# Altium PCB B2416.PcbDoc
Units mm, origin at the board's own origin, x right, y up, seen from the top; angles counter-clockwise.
Board outline 43 x 50 mm, 4 copper layers (Top Layer, Internal 1, Internal 2, Bottom Layer), stack 1.565 mm thick; 60 components, 49 nets, 260 pads, 194 vias.
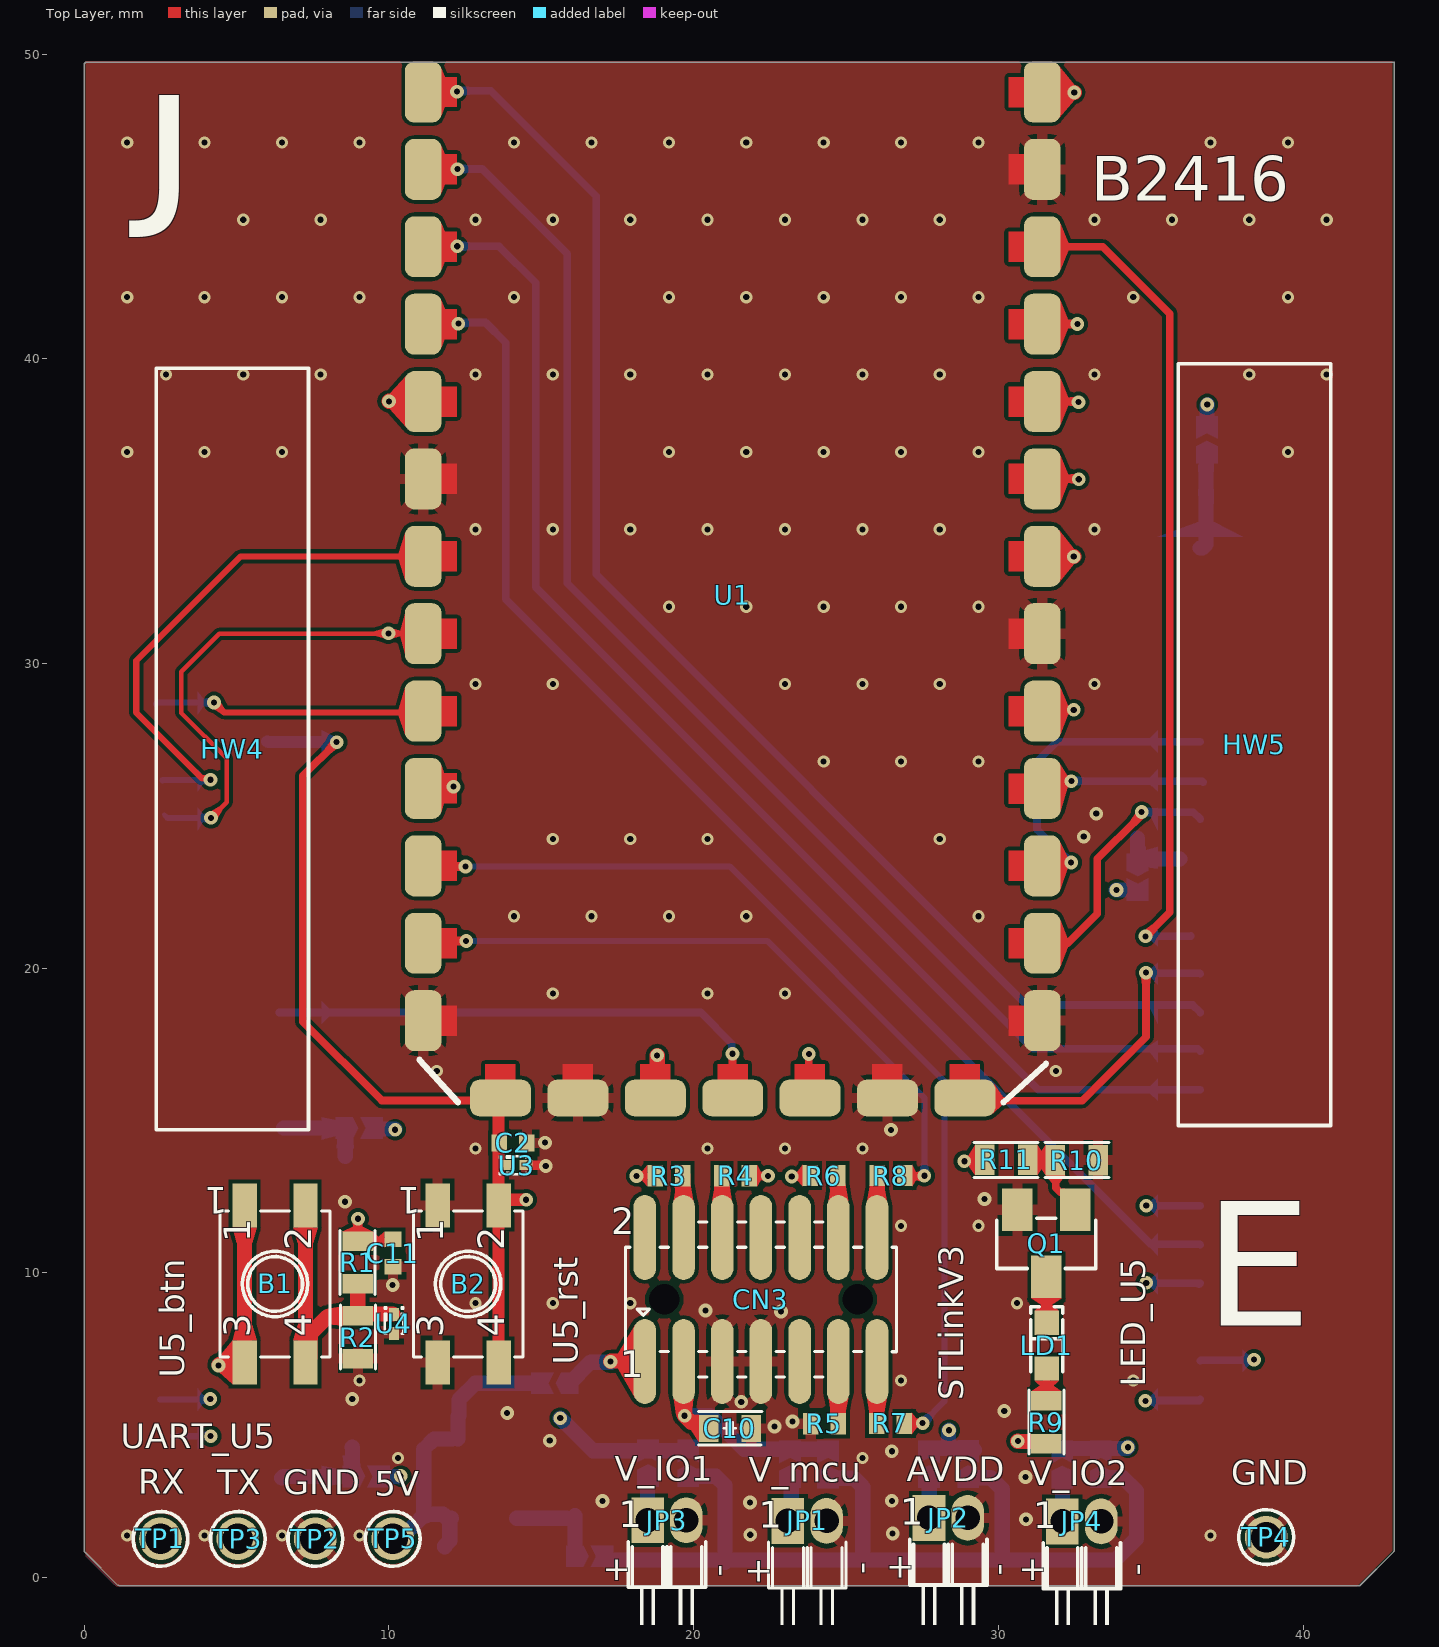
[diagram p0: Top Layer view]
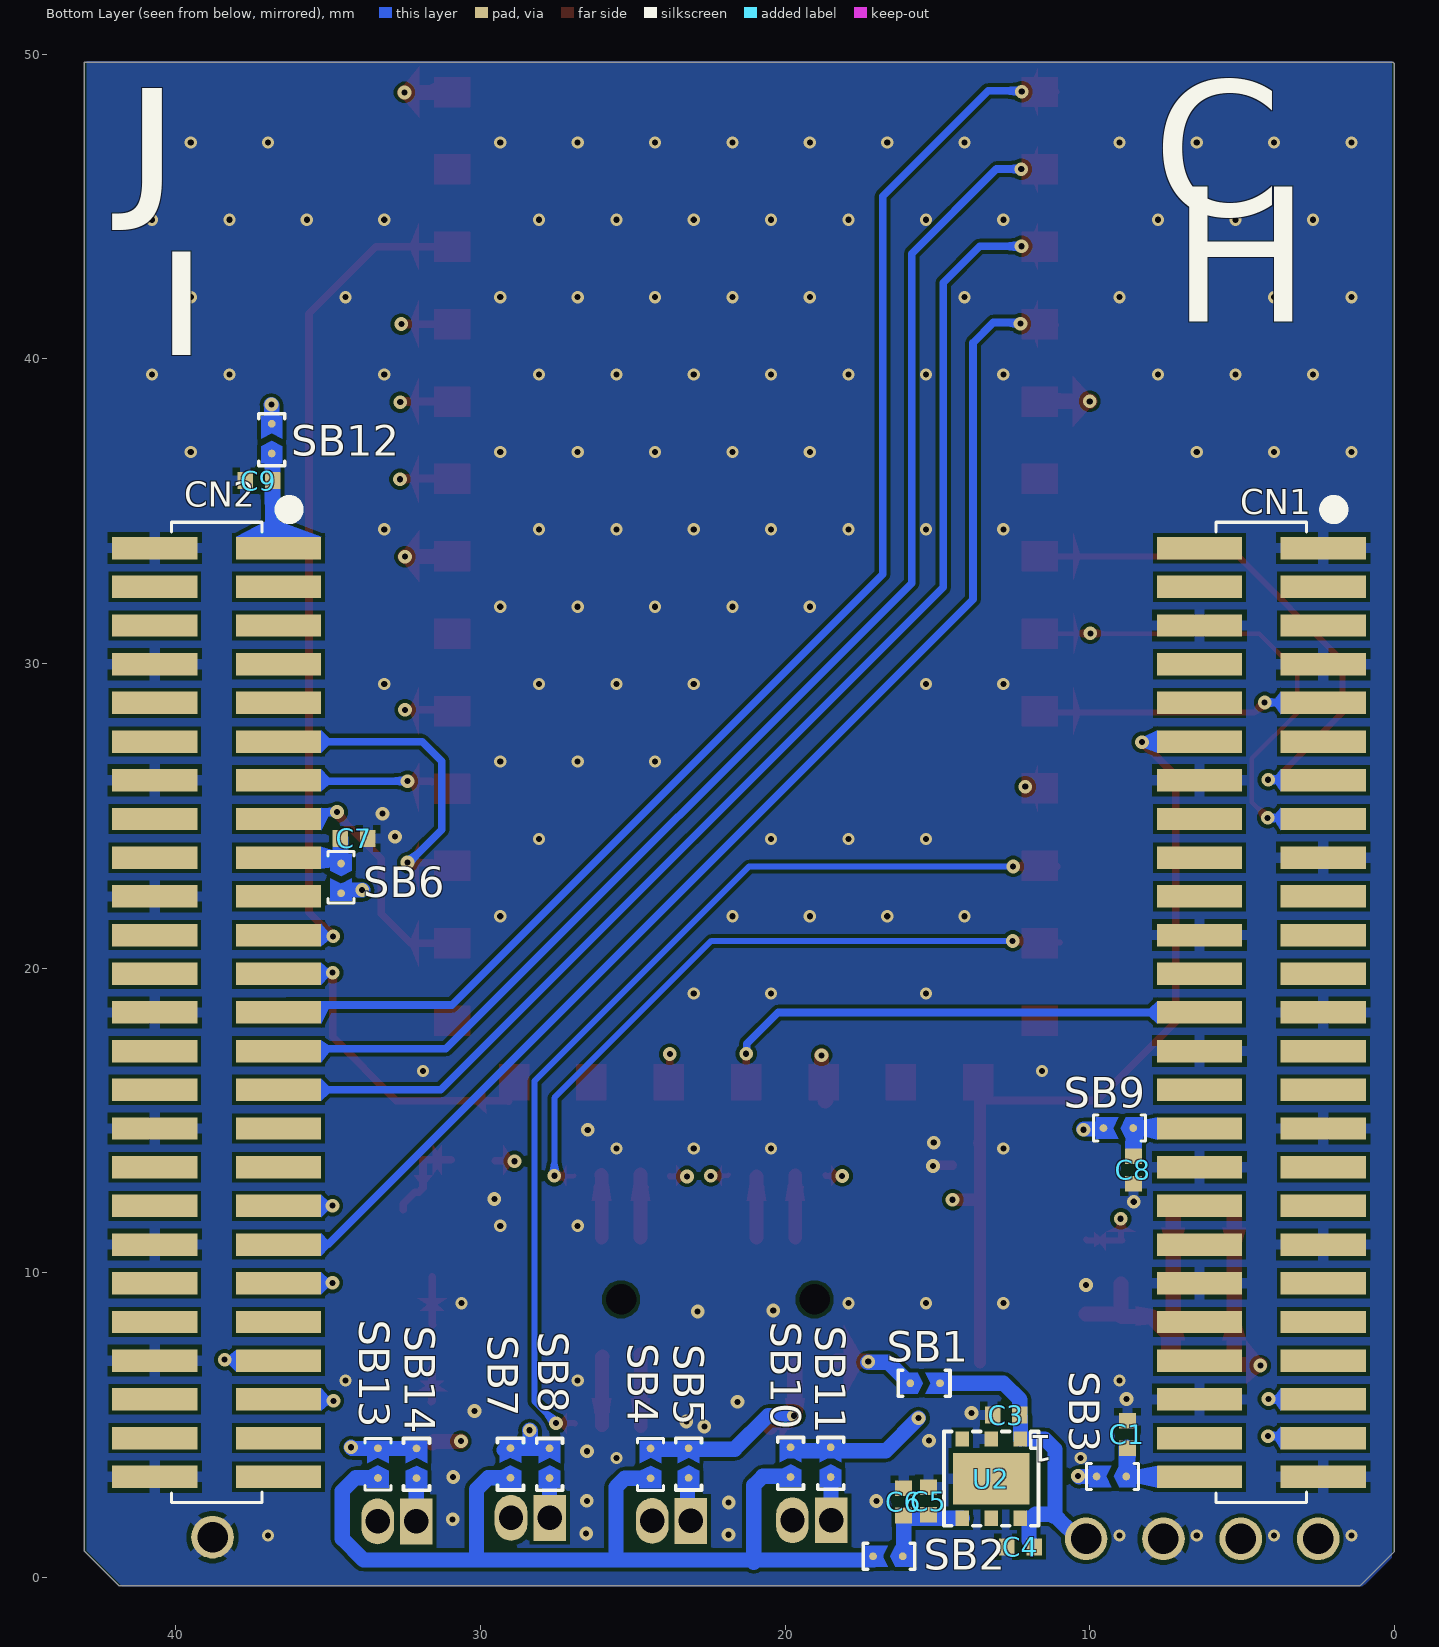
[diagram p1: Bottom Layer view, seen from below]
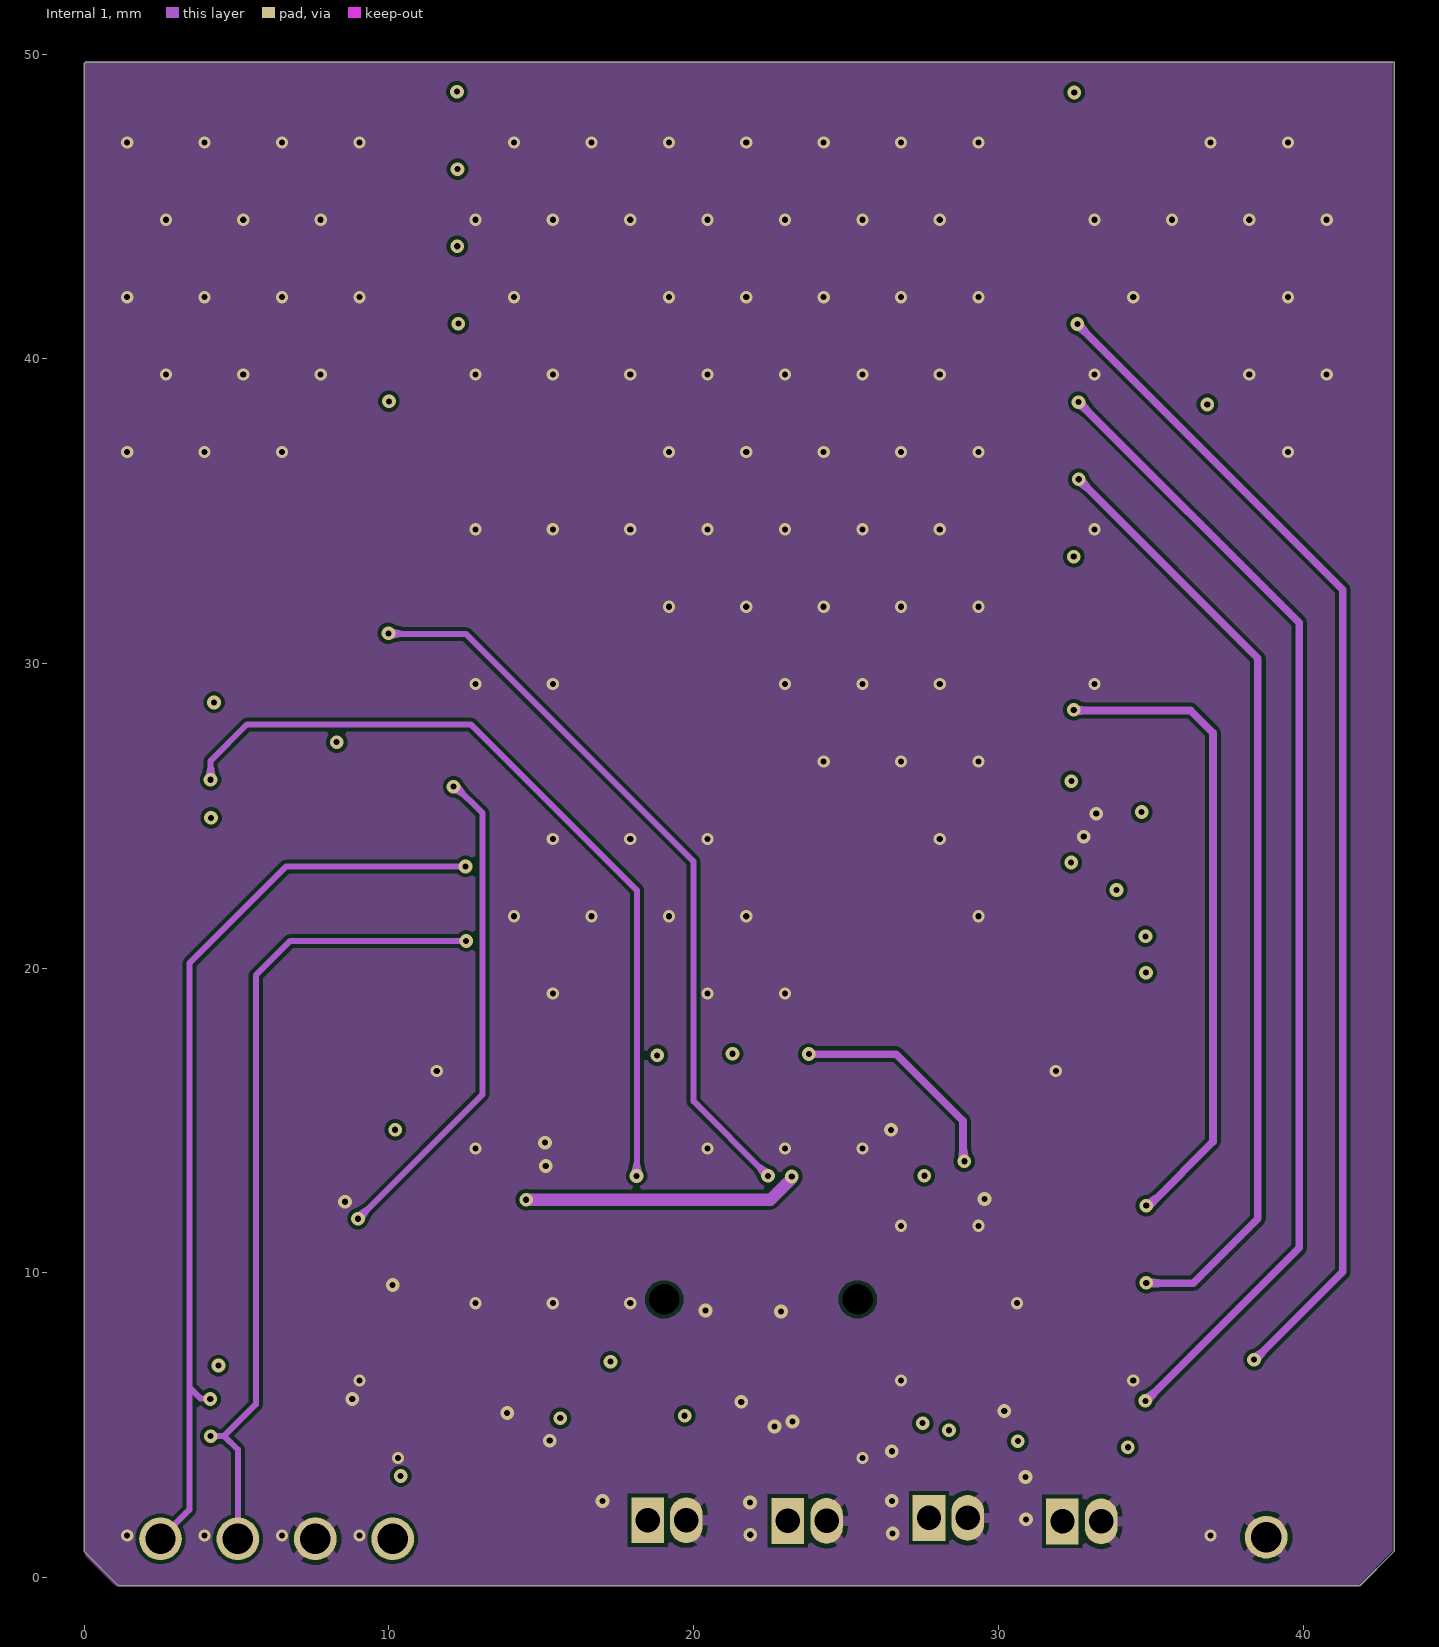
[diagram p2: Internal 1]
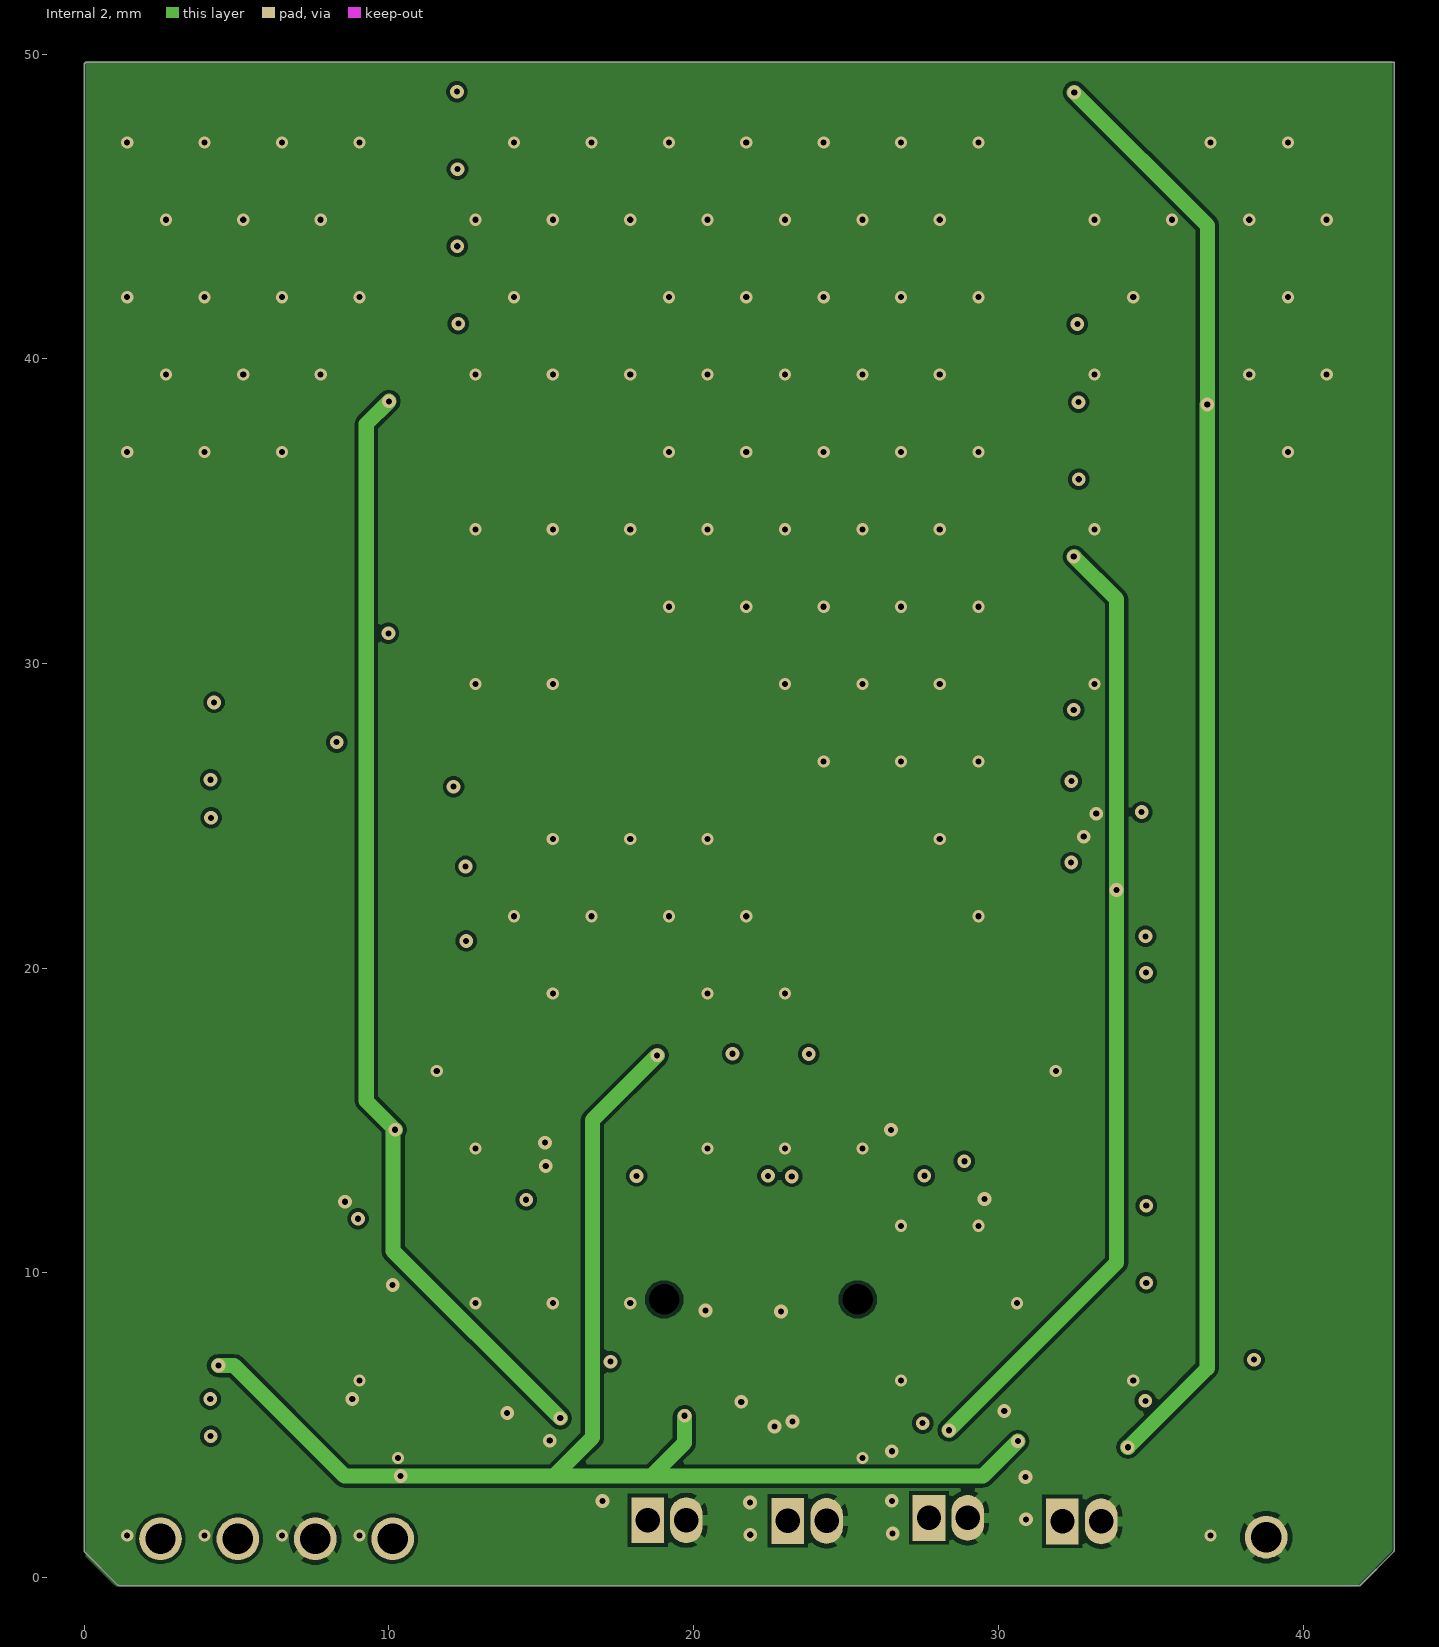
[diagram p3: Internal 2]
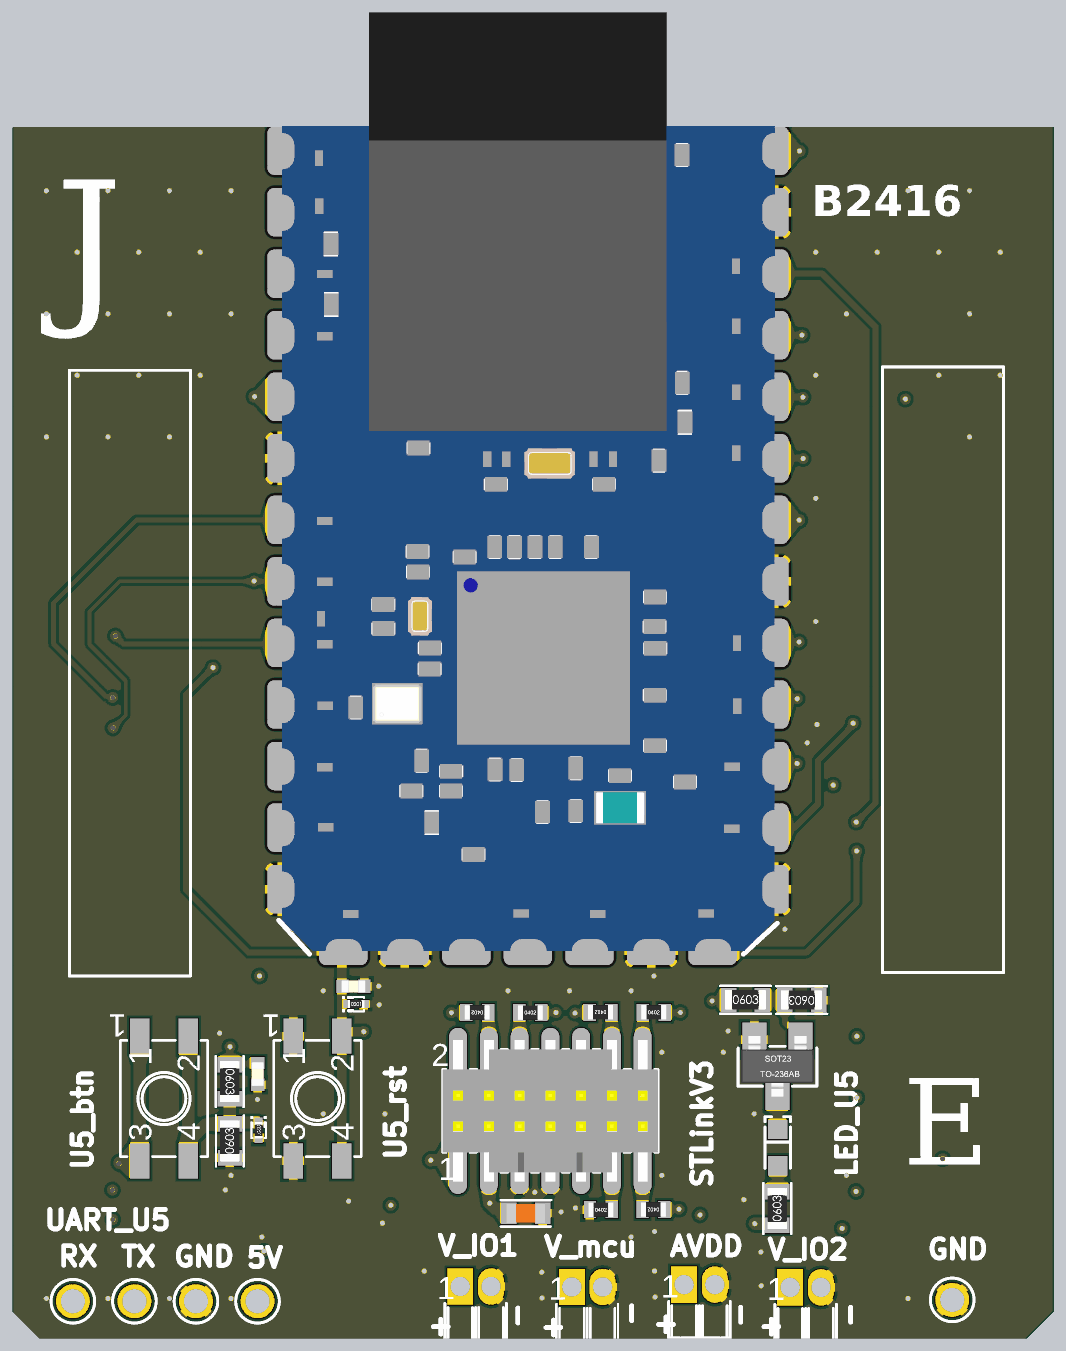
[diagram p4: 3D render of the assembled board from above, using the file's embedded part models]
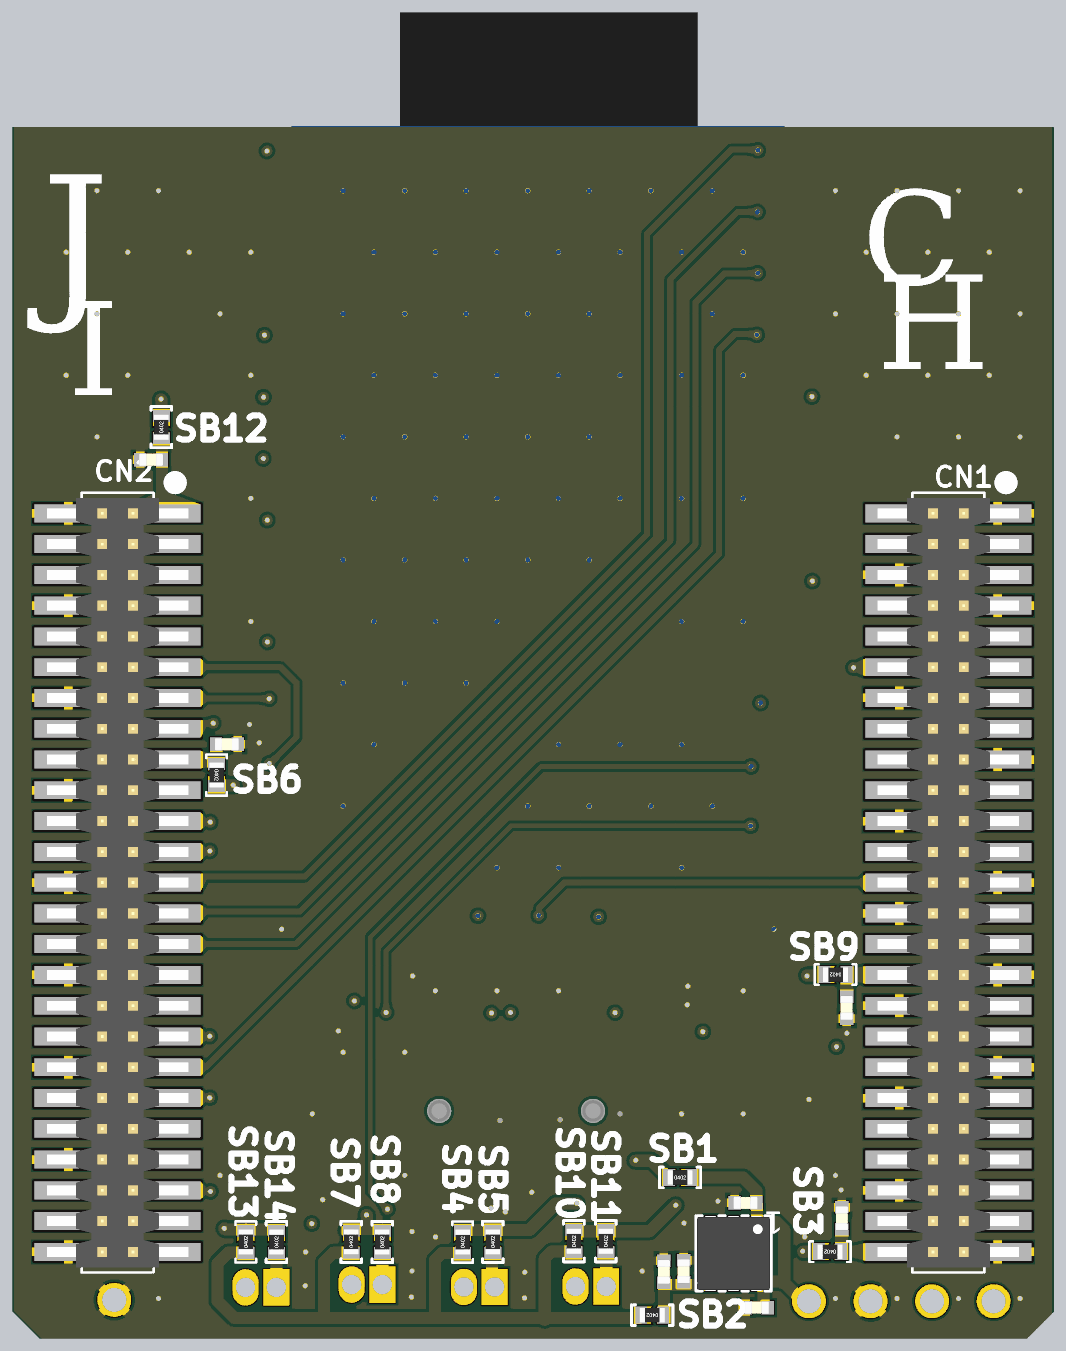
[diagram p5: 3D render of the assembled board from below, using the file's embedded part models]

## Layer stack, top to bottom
Top Solder: solder mask 0.0178, Solder Resist, Dk 3.2
Top Layer: signal copper 0.0406
Dielectric 1: core 0.0762, FR-4, Dk 3.7
Internal 1: signal copper 0.0305
Dielectric 3: prepreg 1.27, Dk 4.5
Internal 2: signal copper 0.0305
Dielectric 2: core 0.0762, Dk 3.7
Bottom Layer: signal copper 0.0406
Bottom Solder: solder mask 0.0178, Solder Resist, Dk 4.2

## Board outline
0,0.852 1.11,-0.258 1.126,-0.258 1.134,-0.267 41.86,-0.267 42.986,0.86 42.995,0.868 43,0.868 43,49.728 42.994,49.733 0.044,49.733 0,49.689

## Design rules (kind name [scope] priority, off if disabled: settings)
Clearance "RF Path 4" [InNet('NetC48_2')] p1: gap=0.125 ignorepadtopadclearanceinfootprint=FALSE
Clearance "RF Path 3" [InNet('NetR12_1')] p2: gap=0.125 ignorepadtopadclearanceinfootprint=FALSE
Clearance "RF Path 2" [InNet('RF_out_ufl')] p3: gap=0.125 ignorepadtopadclearanceinfootprint=FALSE
Clearance "RF Path 1" [InNet('NetR11_1')] p4: gap=0.125 ignorepadtopadclearanceinfootprint=FALSE
Clearance [All] p5: gap=0.12 ignorepadtopadclearanceinfootprint=FALSE
ComponentClearance [All] p1: gap=0.2 collisioncheckmode=3 verticalgap=0.2 showdistances=FALSE
HoleSize [All] p1: absolutevalues=TRUE maxlimit=10 minlimit=0.025 maxpercent=80.000 minpercent=20.000
MinimumSolderMaskSliver [All] p1: minsoldermaskwidth=0.1
PlaneConnect [All] p1: planeconnectstyle=Relief reliefexpansion=0.508 reliefentries=4 reliefconductorwidth=0.21 reliefairgap=0.21
PolygonConnect Path_RF [InNet('NetC12_2')] p1: connectstyle=Direct reliefconductorwidth=0.254 reliefentries=4 polygonreliefangle="90 Angle" airgapwidth=0.254
PolygonConnect PolygonConnect_via [IsVia] p2: connectstyle=Direct reliefconductorwidth=0.254 reliefentries=4 polygonreliefangle="90 Angle" airgapwidth=0.254
PolygonConnect General [All] p3: connectstyle=Relief reliefconductorwidth=0.35 reliefentries=4 polygonreliefangle="90 Angle" conductorbypadedge=TRUE mindistance=0.381 enablemindistance=FALSE airgapwidth=0.15
RoutingVias [All] p1: holewidth=0.3 width=0.8 viastyle="Through Hole" minholewidth=0.1 minwidth=0.2 maxholewidth=3.5 maxwidth=6.5
SilkToSilkClearance [All] p1 off: silktosilkclearance=0.2
SilkToSolderMaskClearance [IsPad] p1 off: minsilkscreentomaskgap=0.2 clearancetoexposedcopper=TRUE
SolderMaskExpansion [All] p1: expansion=0.102 istentingtop=FALSE
Width [All] p1: maxlimit=6 minlimit=0.1 preferedwidth=0.3 minimp=50.000000 maximp=50.000000 favimp=50.000000
24 further rules are at their usual default settings.

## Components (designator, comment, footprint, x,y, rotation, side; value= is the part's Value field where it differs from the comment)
B1 "SW-PUSH-CMS_EVQP2_BLACK" SWI_PANASONIC_EVQP2F02K 6.26,9.636 r90 top value=EVQP2F02K
B2 "SW-PUSH-CMS_EVQP2_BLACK" SWI_PANASONIC_EVQP2F02K 12.597,9.636 r90 top value=EVQP2F02K
C1 "Capacitor" C0402 8.763,4.699 r270 bottom value=10uF
C2 "" C0402 14.076,14.265 r180 top value=100nF
C3 "Capacitor" C0402 12.74,5.333 r180 bottom value=1uF
C4 "Capacitor" C0402 12.271,1.007 r180 bottom value=100nF
C5 "Capacitor" C0402 15.291,2.511 r270 bottom value=1uF
C6 "Capacitor" C0402 16.106,2.487 r270 bottom value=100nF
C7 "Capacitor" C0402 34.143,24.26 r0 bottom value=10uF
C8 "Capacitor" C0402 8.564,13.381 r270 bottom value=10uF
C9 "Capacitor" C0402 37.27,36.001 r0 bottom value=10uF
C10 "Capacitor" C0603 21.189,4.897 r180 top value=1uF
C11 "" C0402 10.128,10.651 r90 top value=100nF
CART-1 "Comment" Sheetbox_6L2S -0.159,-32.344 r0 top
CN1 "FTSH-125-02-L-DV" FTSH-125-02-L-DV 4.366,18.548 r180 bottom locked value="Header 25x2"
CN2 "FTSH-125-02-L-DV" FTSH-125-02-L-DV 38.656,18.548 r180 bottom locked value="Header 25x2"
CN3 "Header 7x2" CON_SAMTEC_FTSH-107-01-L-DV-K-A 22.207,9.127 r0 top
Designator1 "Comment" PCB_SPECIFICATIONS 48.372,6.833 r0 top
HW4 "STICKER_PRODUCT" STICKER_PRODUCT_25X5 4.857,27.194 r90 top value="Sticker product"
HW5 "STICKER_BOARD" STICKER_BOARD_25X5 38.408,27.336 r90 top value="Sticker product"
JP1 "Jumper_Header1.27 2x1 Fitted" CON_WP_707-2-02-2-20-00 23.728,1.859 r0 top value="Header 2x1"
JP2 "Jumper_Header1.27 2x1 Fitted" CON_WP_707-2-02-2-20-00 28.36,1.958 r0 top value="Header 2x1"
JP3 "Jumper_Header1.27 2x1 Fitted" CON_WP_707-2-02-2-20-00 19.123,1.879 r0 top value="Header 2x1"
JP4 "Jumper_Header1.27 2x1 Fitted" CON_WP_707-2-02-2-20-00 32.739,1.842 r0 top value="Header 2x1"
LD1 "LED_red" LED_0603_OSRAM_LS-Q976-NR-1_RED_1A2K_H0P8 31.59,7.61 r90 top value=Red
Q1 "" NPN_SOT23 31.578,10.971 r180 top value=9013-SOT23
R1 "" R0603 8.97,10.337 r270 top value=330R
R2 "" R0603 8.981,7.888 r90 top value=100K
R3 "Resistor" R0402 19.186,13.188 r180 top value=47R
R4 "Resistor" R0402 21.379,13.186 r0 top value=47R
R5 "Resistor" R0402 24.291,5.049 r0 top value=47R
R6 "Resistor" R0402 24.275,13.195 r180 top value=47R
R7 "Resistor" R0402 26.458,5.057 r180 top value=47R
R8 "Resistor" R0402 26.475,13.194 r0 top value=47R
R9 "" R0603 31.574,5.099 r90 top value=1K
R10 "" R0603 32.576,13.703 r180 top value=100K
R11 "" R0603 30.259,13.708 r0 top value=47K
SB1 "SB_ON" SOLDER-BRIDGE_R0402-0R 15.438,6.378 r180 bottom value=0R
SB2 "SB_ON" SOLDER-BRIDGE_R0402-0R 16.588,0.697 r0 bottom value=0R
SB3 "SB_OFF" SOLDER-BRIDGE_R0402-0R 9.251,3.317 r0 bottom
SB4 "SB_ON" SOLDER-BRIDGE_R0402-0R 24.414,3.712 r90 bottom value=0R
SB5 "SB_OFF" SOLDER-BRIDGE_R0402-0R 23.166,3.721 r90 bottom
SB6 "SB_OFF" SOLDER-BRIDGE_R0402-0R 34.572,22.986 r270 bottom
SB7 "SB_ON" SOLDER-BRIDGE_R0402-0R 29.012,3.723 r90 bottom value=0R
SB8 "SB_OFF" SOLDER-BRIDGE_R0402-0R 27.729,3.716 r90 bottom
SB9 "SB_OFF" SOLDER-BRIDGE_R0402-0R 9.024,14.753 r0 bottom
SB10 "SB_ON" SOLDER-BRIDGE_R0402-0R 19.821,3.749 r90 bottom value=0R
SB11 "SB_OFF" SOLDER-BRIDGE_R0402-0R 18.504,3.749 r90 bottom
SB12 "SB_OFF" SOLDER-BRIDGE_R0402-0R 36.848,37.344 r90 bottom
SB13 "SB_ON" SOLDER-BRIDGE_R0402-0R 33.362,3.719 r90 bottom value=0R
SB14 "SB_OFF" SOLDER-BRIDGE_R0402-0R 32.097,3.714 r90 bottom
TP1 "Test_Point_PTH_1mm_2mm" TP_PTH_1MM_1P4MM 2.5,1.27 r90 top value=TP
TP2 "Test_Point_PTH_1mm_2mm" TP_PTH_1MM_1P4MM 7.58,1.27 r90 top value=TP
TP3 "Test_Point_PTH_1mm_2mm" TP_PTH_1MM_1P4MM 5.04,1.27 r90 top value=TP
TP4 "Test_Point_PTH_1mm_2mm" TP_PTH_1MM_1P4MM 38.792,1.327 r90 top value=TP
TP5 "Test_Point_PTH_1mm_2mm" TP_PTH_1MM_1P4MM 10.12,1.27 r90 top value=TP
U1 "MB2248" MB2248_STAMP_FOOTPRINT 13.662,17.25 r0 top
U2 "LD39050PU33R" ICC_DFN6-EPAD_3X3_P095 13.234,3.245 r0 bottom
U3 "ESD-TRANSIL" ESD_ST0201 14.187,13.534 r0 top value=ESDALC6V1-1U2
U4 "" ESD_ST0201 10.163,8.327 r270 top value=ESDALC6V1-1U2

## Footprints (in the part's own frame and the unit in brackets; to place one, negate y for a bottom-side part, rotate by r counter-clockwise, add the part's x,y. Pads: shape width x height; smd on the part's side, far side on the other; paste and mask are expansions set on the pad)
C0402 [mm]
  rect 0.51x0.56 smd mask+0.05: 1(-0.45,0) 2(0.45,0)
  body extent -0.5,-0.3 0.5,0.3, height 0.4
C0603 [mm]
  rect 0.64x0.89 smd mask+0.05: 1(-0.7,0) 2(0.7,0)
  silkscreen extent -1.05,-0.55 1.02,0.55, body extent -0.9,-0.5 0.9,0.5, height 1.4
CON_SAMTEC_FTSH-107-01-L-DV-K-A [mm] "MCD-01959"
  oval 0.74x2.79 smd mask+0.05: 1(-3.81,-2.035) 2(-3.81,2.035) 3(-2.54,-2.035) 4(-2.54,2.035) 5(-1.27,-2.035) 6(-1.27,2.035) 7(0,-2.035) 8(0,2.035) 9(1.27,-2.035) 10(1.27,2.035) 11(2.54,-2.035) 12(2.54,2.035) 13(3.81,-2.035) 14(3.81,2.035)
  round 0 hole 1 unplated paste-2539.97 mask+0.05: NPTH1(-3.175,0) NPTH2(3.175,0)
  silkscreen extent -4.44,-2.54 4.44,2.54, body extent -4.44,-2.92 4.45,2.92, height 6.12
CON_WP_707-2-02-2-20-00 [mm]
  rect 1.07x1.5 hole 0.8 mask+0.05: 1(-0.635,0)
  oval 1.07x1.5 hole 0.8 mask+0.05: 2(0.635,0)
  silkscreen extent -1.27,-5.25 1.27,-0.7, body extent -1.27,-5.25 1.27,0.2, height 2.1
ESD_ST0201 [mm]
  rect 0.425x0.33 smd mask+0.05: 1(-0.312,0) 2(0.312,0)
  silkscreen extent -0.55,-0.3 0.33,0.3, body extent -0.34,-0.18 0.34,0.18, height 0.34
FTSH-125-02-L-DV [mil] "Header2x25 Reverse 1.27mm SAMTEC (FTSH-125-02-L-DV)"
  rect 110x29.02 smd: 1(80,600) 2(-80,600) 3(80,550) 4(-80,550) 5(80,500) 6(-80,500) 7(80,450) 8(-80,450) 9(80,400) 10(-80,400) 11(80,350) 12(-80,350) 13(80,300) 14(-80,300) 15(80,250) 16(-80,250) 17(80,200) 18(-80,200) 19(80,150) 20(-80,150) 21(80,100) 22(-80,100) 23(80,50) 24(-80,50) 25(80,0) 26(-80,0) 27(80,-50) 28(-80,-50) 29(80,-100) 30(-80,-100) 31(80,-150) 32(-80,-150) 33(80,-200) 34(-80,-200) 35(80,-250) 36(-80,-250) 37(80,-300) 38(-80,-300) 39(80,-350) 40(-80,-350) 41(80,-400) 42(-80,-400) 43(80,-450) 44(-80,-450) 45(80,-500) 46(-80,-500) 47(80,-550) 48(-80,-550) 49(80,-600) 50(-80,-600)
  silkscreen extent -58,-633 103,659, body extent -115,-625 115,625, height 190
ICC_DFN6-EPAD_3X3_P095 [mm]
  rect 0.45x0.5 smd mask+0.05: 1(-0.95,-1.3) 2(0,-1.3) 3(0.95,-1.3) 4(0.95,1.3) 5(0,1.3) 6(-0.95,1.3)
  rect 2.5x1.7 smd mask+0.05: EP(0,0)
  silkscreen extent -1.55,-1.55 1.55,1.55, body extent -1.55,-1.55 1.55,1.55, height 1
LED_0603_OSRAM_LS-Q976-NR-1_RED_1A2K_H0P8 [mm]
  rect 0.8x0.8 smd mask+0.05: 1(-0.75,0) 2(0.75,0)
  silkscreen extent -0.85,-0.53 1.28,0.53, body extent -0.85,-0.45 0.85,0.45, height 0.8
MB2248_STAMP_FOOTPRINT [mm]
  rrect50% 1.2x2 smd mask+0.102: 1(-2.54,31.509) 2(-2.54,28.969) 3(-2.54,26.429) 4(-2.54,23.889) 5(-2.54,21.349) 6(-2.54,18.809) 7(-2.54,16.269) 8(-2.54,13.729) 9(-2.54,11.189) 10(-2.54,8.649) 11(-2.54,6.109) 12(-2.54,3.569) 13(-2.54,1.029) 21(17.78,1.029) 22(17.78,3.569) 23(17.78,6.109) 24(17.78,8.649) 25(17.78,11.189) 26(17.78,13.729) 27(17.78,16.269) 28(17.78,18.809) 29(17.78,21.349) 30(17.78,23.889) 31(17.78,26.429) 32(17.78,28.969) 33(17.78,31.509)
  rrect50% 2x1.2 smd mask+0.102: 14(0,-1.511) 15(2.54,-1.511) 16(5.08,-1.511) 17(7.62,-1.511) 18(10.16,-1.511) 19(12.7,-1.511) 20(15.24,-1.511)
  Top Layer region: 14.734,-0.4 14.734,-1.6 15.734,-1.6 15.734,-0.4
  Top Layer region: 0.494,-1.6 0.494,-0.4 -0.506,-0.4 -0.506,-1.6
  Top Layer region: 2.034,-0.4 2.034,-1.6 3.034,-1.6 3.034,-0.4
  Top Layer region: 4.574,-0.4 4.574,-1.6 5.574,-1.6 5.574,-0.4
  Top Layer region: 7.114,-0.4 7.114,-1.6 8.114,-1.6 8.114,-0.4
  Top Layer region: 9.654,-0.4 9.654,-1.6 10.654,-1.6 10.654,-0.4
  Top Layer region: 12.194,-0.4 12.194,-1.6 13.194,-1.6 13.194,-0.4
  Top Layer region: -1.424,19.309 -2.624,19.309 -2.624,18.309 -1.424,18.309
  Top Layer region: -1.424,21.849 -2.624,21.849 -2.624,20.849 -1.424,20.849
  Top Layer region: -1.424,24.389 -2.624,24.389 -2.624,23.389 -1.424,23.389
  Top Layer region: -1.424,26.929 -2.624,26.929 -2.624,25.929 -1.424,25.929
  Top Layer region: -1.424,29.469 -2.624,29.469 -2.624,28.469 -1.424,28.469
  Top Layer region: -2.624,31.009 -1.424,31.009 -1.424,32.009 -2.624,32.009
  Top Layer region: -1.424,16.769 -2.624,16.769 -2.624,15.769 -1.424,15.769
  Top Layer region: -1.424,14.229 -2.624,14.229 -2.624,13.229 -1.424,13.229
  Top Layer region: -1.424,11.689 -2.624,11.689 -2.624,10.689 -1.424,10.689
  Top Layer region: -1.424,9.149 -2.624,9.149 -2.624,8.149 -1.424,8.149
  Top Layer region: -1.424,6.609 -2.624,6.609 -2.624,5.609 -1.424,5.609
  Top Layer region: -1.424,4.069 -2.624,4.069 -2.624,3.069 -1.424,3.069
  Top Layer region: -1.424,1.529 -2.624,1.529 -2.624,0.529 -1.424,0.529
  Top Layer region: 17.867,19.307 16.667,19.307 16.667,18.307 17.867,18.307
  Top Layer region: 17.867,21.847 16.667,21.847 16.667,20.847 17.867,20.847
  Top Layer region: 17.867,24.387 16.667,24.387 16.667,23.387 17.867,23.387
  Top Layer region: 17.867,26.927 16.667,26.927 16.667,25.927 17.867,25.927
  Top Layer region: 17.867,29.467 16.667,29.467 16.667,28.467 17.867,28.467
  Top Layer region: 16.667,31.007 17.867,31.007 17.867,32.007 16.667,32.007
  Top Layer region: 17.867,16.767 16.667,16.767 16.667,15.767 17.867,15.767
  Top Layer region: 17.867,14.227 16.667,14.227 16.667,13.227 17.867,13.227
  Top Layer region: 17.867,11.687 16.667,11.687 16.667,10.687 17.867,10.687
  Top Layer region: 17.867,9.147 16.667,9.147 16.667,8.147 17.867,8.147
  Top Layer region: 17.867,6.607 16.667,6.607 16.667,5.607 17.867,5.607
  Top Layer region: 17.867,4.067 16.667,4.067 16.667,3.067 17.867,3.067
  Top Layer region: 17.867,1.527 16.667,1.527 16.667,0.527 17.867,0.527
  silkscreen extent -2.67,-1.65 17.91,-0.25, body extent -2.52,-1.53 17.81,37.21, height 2.6
NPN_SOT23 [mm]
  rect 1x1.4 smd mask+0.05: 1(-0.95,-1.1) 2(0.95,-1.1) 3(0,1.1)
  silkscreen extent -1.63,-0.82 1.63,0.82, body extent -1.56,-1.25 1.56,1.25, height 1.1
PCB_SPECIFICATIONS [mm]
R0402 [mm]
  rect 0.51x0.7 smd mask+0.05: 1(-0.45,0) 2(0.45,0)
  body extent -0.52,-0.3 0.52,0.3, height 0.4
R0603 [mm]
  rect 0.64x1 smd mask+0.05: 1(-0.7,0) 2(0.7,0)
  silkscreen extent -1.05,-0.58 1.05,0.58, body extent -0.9,-0.5 0.9,0.5, height 0.56
Sheetbox_6L2S [mil] "Sheetbox 6 layers / 2 silkscreens"
  round 20 on Mech16: 1(813.5,208.05) 1(2736.63,208.05)
SOLDER-BRIDGE_R0402-0R [mil] "MCD-01619"
  round 10 smd paste-393.7: 1(-17.72,0) 2(20.67,0)
  Top Layer region: -30.51,-13.78 -30.51,13.78 -8.37,13.78 -1.48,0 -8.37,-13.78
  Top Layer region: 1.48,13.78 8.37,0 1.48,-13.78 30.51,-13.78 30.51,13.78
  silkscreen extent -33,-17 33,17, body extent -20,-12 20,12, height 14
STICKER_BOARD_25X5 [mm] "Sticker to mention board reference + serial number"
  silkscreen extent -12.5,-2.5 12.5,2.5, body extent -12.5,-2.5 12.5,2.5, height 0.01
STICKER_PRODUCT_25X5 [mm] "Sticker to mention board CPN code"
  silkscreen extent -12.5,-2.5 12.5,2.5
SWI_PANASONIC_EVQP2F02K [mm]
  rect 1.45x0.8 smd mask+0.05: 1(2.575,1) 2(2.575,-1) 3(-2.575,1) 4(-2.575,-1)
  silkscreen extent -2.4,-1.8 2.4,1.8, body extent -2.9,-1.8 2.9,1.8, height 2.7
TP_PTH_1MM_1P4MM [mm] "MCD-03401"
  round 1.4 hole 1 mask+0.05: 1(0,0)
  silkscreen extent -0.9,-0.9 0.9,0.9

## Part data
B1 B2: library part MCD-00168, "EVQP2 - 4.7mm x 3.5 mm SMD Light Touch Switch", Manufacturer=PANASONIC, Manufacturer_Part_Number=EVQP2F02K
C1 C7 C8 C9: library part MCD-01532, "Capacitor, MLCC, 10uF, 10V, X5R, +/-20%, 0402, T=0.5mm", Manufacturer=MURATA, Manufacturer_Part_Number=GRM155R61A106ME11, Package=0402
C2 C11: library part MCD-00006, "Capacitor, MLCC, 100nF, 16V, X7R, 10%, 0402, T=0.5mm", Alternate_Manufacturer=MURATA, Alternate_Manufacturer_Part_Number=GCM155R71C104KA55D, Manufacturer=YAGEO, Manufacturer_Part_Number=CC0402KRX7R7BB104, Package=C0402
C3 C5: library part MCD-03432, "Capacitor, MLCC, 1uF, 6.3V, X5R, +/- 10%, 0402, T=0.5mm", Manufacturer=MURATA, Manufacturer_Part_Number=GRM155R70J105KA12, Package=0402
C4 C6: library part MCD-00102, "Capacitor, MLCC, 100nF, 16V, X7R, +/-10%, 0402, T=0.5mm", Manufacturer=YAGEO, Manufacturer_Part_Number=CC0402KRX7R7BB104, Package=0402
C10: library part MCD-00010, "Capacitor, MLCC, 1uF, 16V, X5R, 10%, 0603, T=0,8mm", Manufacturer=YAGEO, Manufacturer_Part_Number=CC0603KRX5R7BB105, Package=C0603
CN1 CN2: library part MCD-02746, "Header, 25x2, 12.7mm, VR, SMD, T=4.83mm", Manufacturer=SAMTEC
CN3: library part MCD-01531, "Header, 7x2, 1.27mm, VR, T=5.97mm, FTSH series STDC14 without Alignment Pin", Manufacturer=SAMTEC, Manufacturer_Part_Number=FTSH-107-01-L-DV-K
HW4 HW5: library part MCD-02189, "Sticker product 25x5 mm", Alternate_Manufacturer=N/A
JP1 JP2 JP3 JP4: library part MCD-01428, "Header, 2x1, 1.27mm, RA, TH, T=3.05mm/2.29mm", Manufacturer="W&P PRODUCTS", Manufacturer_Part_Number=707-2-02-2-20-00
LD1: library part MCD-00586, "LED, Red, 2V, 20mA, 0603", Manufacturer="OSRAM OPTO SEMICONDUCTORS", Manufacturer_Part_Number="LS Q976-NR-1", Package=0603
Q1: library part MCD-00073, "NPN Bipolar Transistor", Manufacturer=NXP, Manufacturer_Part_Number=BSR14
R1: library part MCD-00197, "Resistor,330R,0603,1%,1/10W", Manufacturer=YAGEO, Manufacturer_Part_Number=RC0603FR-07330RL, Package=R0603
R2 R10: library part MCD-00223, "Resistor,100K,0603,1%,1/10W", Manufacturer=YAGEO, Manufacturer_Part_Number=RC0603FR-07100KL, Package=R0603
R3 R4 R5 R6 R7 R8: library part MCD-00481, "Resistor,47R,0402,1%,1/16W", Manufacturer=YAGEO, Manufacturer_Part_Number=RC0402FR-0747RL, Package=R0402
R9: library part MCD-00070, "Resistor,1K,0603,1%,1/10W", Manufacturer=YAGEO, Manufacturer_Part_Number=RC0603FR-071KL, Package=R0603
R11: library part MCD-00222, "Resistor,47K,0603,1%,1/10W", Manufacturer=YAGEO, Manufacturer_Part_Number=RC0603FR-0747KL, Package=R0603
SB1 SB2 SB4 SB7 SB10 SB13: library part MCD-01618, "Resistor, 0R, SB0402, 5%, 0.063W", Manufacturer=YAGEO, Manufacturer_Part_Number=RC0402JR-070RL, Package=0402
SB3 SB5 SB6 SB8 SB9 SB11 SB12 SB14: library part MCD-02162, "Solder Bridge 0402 OFF", Manufacturer=YAGEO, Manufacturer_Part_Number=RC0402JR-070RL, Package=SB0402
TP1 TP2 TP3 TP4 TP5: library part MCD-03401, "Test Point trought hole 1mm/1.4mm", Manufacturer=N/A
U2: library part MCD-00215, "Low quiescent current and low noise voltage regulators", Manufacturer=STMICROELECTRONICS, Manufacturer_HQ_COO=EU, Package="DFN6 3x3mm"
U3: library part MCD-00170, "ESD protection 6V1", Manufacturer=STMICROELECTRONICS, Manufacturer_HQ_COO=EU, Manufacturer_Part_Number=ESDALC6V1-1U2
U4: library part MCD-00170, "ESD protection 6V1", Manufacturer=STMICROELECTRONICS, Manufacturer_Part_Number=ESDALC6V1-1U2

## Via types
v1: diameter 0.4/0.4/0.4/0.4 (per signal layer), hole 0.2, Top Layer to Bottom Layer, tented both sides, 117 vias
v2: diameter 0.45, hole 0.2, Top Layer to Bottom Layer, tented both sides, 77 vias

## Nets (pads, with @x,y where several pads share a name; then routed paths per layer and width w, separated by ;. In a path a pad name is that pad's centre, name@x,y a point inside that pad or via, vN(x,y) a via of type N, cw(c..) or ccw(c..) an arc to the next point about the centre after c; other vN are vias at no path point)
5V_STDC14: CN3.1 SB1.1 | length 2.7
  Top Layer w0.5: v2(17.271,7.087) 17.289,7.104 CN3.1@18.31,7.104
  Bottom Layer w0.5: SB1.1@15.904,6.354 16.619,7.069 v2@17.289,7.069
AVDD33: SB6.2 SB7.2 SB8.2 U1.27 | length 35.1
  Top Layer w0.5: U1.27@31.509,33.532 31.531,33.509 v2(32.475,33.509)
  Internal 2 w0.5: v2(28.384,4.834) 33.882,10.332 v2(33.882,22.57) 33.882,32.112 v2@32.489,33.504
  Bottom Layer w0.5: SB8.2@27.74,4.246 28.364,4.246 ; v2(28.384,4.834) 28.364,4.815 28.364,4.246 ; SB7.2@28.964,4.246 28.364,4.246 ; 29.163,4.238 29.214,4.187 ; v2@33.859,22.563 34.47,22.563 SB6.2
BOOT0_U5: CN1.9 U1.9 | length 8.9
  Top Layer w0.2: v2(4.259,28.722) 4.587,28.394 U1.9@11.086,28.394
  Bottom Layer w0.2: CN1.9@2.358,28.677 2.403,28.722 v2(4.259,28.722)
BOOT_WW6: CN2.29 U1.3 | length 42.6
  Top Layer w0.25: U1.3@11.383,43.681 11.397,43.695 v2(12.24,43.695)
  Bottom Layer w0.25: v2(12.24,43.695) 13.61,43.695 14.811,42.493 14.811,32.506 31.309,16.008 CN2.29
CHIP-EN: CN2.35 U1.25 | length 24.3
  Top Layer w0.25: U1.25@31.358,28.559 31.436,28.481 v2(32.474,28.481)
  Internal 1 w0.25: v2(32.474,28.481) 32.474,28.465 32.466,28.458 36.319,28.458 37.044,27.732 37.044,14.302 35.048,12.305 35.01,12.305 34.91,12.205 v2(34.856,12.205)
  Bottom Layer w0.25: v2@34.882,12.181 34.902,12.201 36.621,12.201 CN2.35
Device_Ready: CN2.39 U1.28 | length 34.2
  Top Layer w0.25: U1.28 31.456,36.072 v2@32.582,36.072
  Internal 1 w0.25: v2(32.639,36.05) 38.521,30.168 38.521,11.779 36.4,9.659 34.868,9.659 v2(34.856,9.672)
  Bottom Layer w0.25: v2@34.851,9.65 34.866,9.665 36.549,9.665 36.586,9.628 36.616,9.658 CN2.39
Device_WUP: CN2.23 U1.20 | length 10.5
  Top Layer w0.25: U1.20@29.077,15.638 29.094,15.656 32.76,15.656 34.849,17.744 v2(34.849,19.856)
  Bottom Layer w0.25: v2@34.878,19.844 34.885,19.837 36.605,19.837 CN2.23
Ext_32k: CN1.26 U1.17 | length 17
  Top Layer w0.25: U1.17@21.273,15.775 21.283,15.785 21.276,15.791 v2(21.276,17.191)
  Bottom Layer w0.25: CN1.26 20.227,18.548 21.256,17.519 21.256,17.212 v2(21.276,17.191)
Ext_AVDD33: C7.2 CN2.17 SB6.1 | length 2.3
  Bottom Layer w0.5: C7.2@34.572,24.262 SB6.1 34.718,23.582 CN2.17@35.965,23.582
Ext_VDD_IO_1: C8.1 CN1.32 SB9.1 | length 3
  Bottom Layer w0.5: CN1.32@6.538,14.759 6.544,14.753 SB9.1 ; C8.1 8.564,14.73 SB9.1@8.606,14.771
Ext_VDD_IO_2: C9.1 CN2.1 SB12.1 | length 3.2
  Bottom Layer w0.5: CN2.1 36.702,33.788 36.82,33.907 36.82,36.807 SB12.1@36.877,36.864
Ext_VDD_MCU: C1.2 CN1.50 SB3.1 | length 3.3
  Bottom Layer w0.5: CN1.50@6.482,3.267 6.532,3.317 SB3.1 8.801,4.271 C1.2@8.795,4.277
GND: B2.1 B2.3 C1.1 C2.1 C3.1 C4.1 C5.1 C6.1 C7.1 C8.2 C9.2 C10.1 C11.1 CN1.1 CN1.6 CN1.7 CN1.14 CN1.17 CN1.22 CN1.25 CN1.28 CN1.31 CN1.34 CN1.37 CN1.40 CN1.46 CN1.49 CN2.2 CN2.8 CN2.14 CN2.20 CN2.26 CN2.32 CN2.38 CN2.44 CN2.50 CN3.5 CN3.7 JP1.2 JP2.2 JP3.2 JP4.2 Q1.2 R2.1 R5.1 R10.1 TP2.1 TP4.1 U1.6 U1.13 U1.15 U1.19 U1.21 U1.26 U1.32 U2.2 U2.EP U3.2 U4.2 | length 0.7
  Top Layer w0.3: U3.2 15.132,13.534 v2@15.15,13.516
  other v1: 1.407,1.385 3.947,1.385 6.487,1.385 9.027,1.385 36.967,1.385 10.297,3.925 25.537,3.925 9.027,6.465 26.807,6.465 34.427,6.465 12.837,9.005 15.377,9.005 17.917,9.005 30.617,9.005 26.807,11.545 29.347,11.545 12.837,14.085 20.457,14.085 22.997,14.085 25.537,14.085 11.567,16.625 31.887,16.625 15.377,19.165 20.457,19.165 22.997,19.165 14.107,21.705 16.647,21.705 19.187,21.705 21.727,21.705 29.347,21.705 15.377,24.245 17.917,24.245 20.457,24.245 28.077,24.245 24.267,26.785 26.807,26.785 29.347,26.785 12.837,29.325 15.377,29.325 22.997,29.325 25.537,29.325 28.077,29.325 33.157,29.325 19.187,31.865 21.727,31.865 24.267,31.865 26.807,31.865 29.347,31.865 12.837,34.405 15.377,34.405 17.917,34.405 20.457,34.405 22.997,34.405 25.537,34.405 28.077,34.405 33.157,34.405 1.407,36.945 3.947,36.945 6.487,36.945 19.187,36.945 21.727,36.945 24.267,36.945 26.807,36.945 29.347,36.945 39.507,36.945 2.677,39.485 5.217,39.485 7.757,39.485 12.837,39.485 15.377,39.485 17.917,39.485 20.457,39.485 22.997,39.485 25.537,39.485 28.077,39.485 33.157,39.485 38.237,39.485 40.777,39.485 1.407,42.025 3.947,42.025 6.487,42.025 9.027,42.025 14.107,42.025 19.187,42.025 21.727,42.025 24.267,42.025 26.807,42.025 29.347,42.025 34.427,42.025 39.507,42.025 2.677,44.565 5.217,44.565 7.757,44.565 12.837,44.565 15.377,44.565 17.917,44.565 20.457,44.565 22.997,44.565 25.537,44.565 28.077,44.565 33.157,44.565 35.697,44.565 38.237,44.565 40.777,44.565 1.407,47.105 3.947,47.105 6.487,47.105 9.027,47.105 14.107,47.105 16.647,47.105 19.187,47.105 21.727,47.105 24.267,47.105 26.807,47.105 29.347,47.105 36.967,47.105 39.507,47.105
  other v2: 21.858,1.406 26.53,1.442 30.91,1.909 21.85,2.466 17.004,2.515 26.506,2.518 30.894,3.303 26.503,4.146 15.277,4.492 22.651,4.956 23.241,5.119 13.878,5.4 30.193,5.464 21.561,5.767 8.793,5.863 22.869,8.73 20.388,8.763 10.12,9.6 8.556,12.333 29.543,12.425 15.144,13.506 15.12,14.273 26.477,14.695 32.805,24.317 33.213,25.073
JTCK: CN2.27 U1.2 | length 43.8
  Top Layer w0.25: U1.2@11.195,46.252 11.221,46.226 v2(12.248,46.226)
  Bottom Layer w0.25: v2@12.213,46.232 13.061,46.232 15.845,43.448 15.845,32.643 31.136,17.352 36.55,17.352 CN2.27
JTDI: CN2.37 U1.4 | length 43
  Top Layer w0.25: U1.4@11.133,41.117 11.172,41.156 v2(12.276,41.156)
  Bottom Layer w0.25: v2(12.276,41.156) 12.313,41.194 13.167,41.194 13.83,40.531 13.83,32.105 34.998,10.937 36.615,10.937 CN2.37
JTMS: CN2.25 U1.1 | length 45.3
  Top Layer w0.25: U1.1@11.11,48.763 11.118,48.77 v2(12.23,48.77)
  Bottom Layer w0.25: v2(12.23,48.77) 12.259,48.798 13.336,48.798 16.8,45.334 16.8,32.93 30.938,18.791 36.381,18.791 CN2.25
NetB1_2: B1.2 B1.4 R1.2 R2.2 U4.1 | length 10.1
  Top Layer w0.5: B1.2@7.327,12.227 7.26,12.16 B1.4 7.41,7.211 7.41,7.998 7.983,8.571 R2.2@8.95,8.571 ; R1.2 8.976,9.632 R2.2@8.976,8.658 ; R2.2@8.974,8.595 R2.2@8.981,8.602 ; R2.2 9.039,8.646 U4.1@10.122,8.646
NetC3_2: C3.2 C4.2 SB1.2 TP5.1 U2.1 U2.6 | length 10.6
  Bottom Layer w0.5: TP5.1 10.364,1.27 10.761,1.668 10.773,1.668 11.184,2.079 11.776,2.079 11.91,1.945 ; 11.206,2.025 11.141,2.089 11.141,4.21 11.475,4.545 U2.1@12.064,4.545 ; C4.2 11.826,1.012 11.826,1.037 11.996,1.207 11.996,1.901 12.04,1.945 ; U2.1@12.269,4.559 12.269,5.287 12.29,5.308 C3.2 12.295,5.338 12.295,5.839 12.835,6.378 SB1.2
NetC5_2: C5.2 C6.2 SB2.1 U2.4 | length 3
  Bottom Layer w0.5: U2.4 C6.2@15.833,1.945 ; SB2.1@16.106,0.682 C6.2
NetCN3_4: CN3.4 R3.1 | length 2
  Top Layer w0.45: CN3.4 19.667,13.201 R3.1@19.67,13.204
NetCN3_6: CN3.6 R4.1 | length 2
  Top Layer w0.45: R4.1@20.932,13.16 20.937,13.155 CN3.6
NetCN3_11: CN3.11 R5.2 | length 2.4
  Top Layer w0.45: R5.2@24.735,4.97 24.735,7.315 CN3.11@24.749,7.329
NetCN3_12: CN3.12 R6.1 | length 2.1
  Top Layer w0.45: R6.1@24.745,13.234 24.747,13.232 CN3.12
NetCN3_13: CN3.13 R7.2 | length 2.3
  Top Layer w0.45: CN3.13@25.993,7.265 26.01,7.249 R7.2@26.01,4.994
NetCN3_14: CN3.14 R8.1 | length 2.1
  Top Layer w0.45: CN3.14 26.017,13.193 R8.1@26.036,13.211
NetJP1_1: JP1.1 SB5.1 | length 1.4
  Bottom Layer w0.5: JP1.1 23.205,1.971 SB5.1@23.205,3.258
NetJP2_1: JP2.1 SB8.1 | length 1.4
  Bottom Layer w0.5: JP2.1@27.729,1.92 SB8.1 ; JP2.1@27.928,1.912 JP2.1@27.951,1.89
NetJP3_1: JP3.1 SB11.1 | length 1.4
  Bottom Layer w0.5: JP3.1 SB11.1@18.488,3.271
NetJP4_1: JP4.1 SB14.1 | length 1.4
  Bottom Layer w0.5: JP4.1 SB14.1@32.104,3.272
NetLD1_1: LD1.1 R9.2 | length 1.1
  Top Layer w0.25: LD1.1 31.59,5.79 R9.2@31.614,5.766
NetLD1_2: LD1.2 Q1.3 | length 1.6
  Top Layer w0.25: LD1.2@31.565,8.302 31.578,8.315 Q1.3
NetQ1_1: Q1.1 R10.2 R11.2 | length 2.9
  Top Layer w0.25: R11.2 R10.2@31.876,13.708 ; R10.2@31.884,13.682 31.884,12.792 32.03,12.646 32.153,12.646 32.528,12.271 Q1.1
NetSB2_2: SB2.2 SB4.1 SB7.1 SB10.1 SB13.1 | length 31.8
  Bottom Layer w0.5: SB2.2@17.022,0.655 17.098,0.58 21.025,0.58 25.553,0.58 ; SB10.1@19.826,3.322 20.732,3.322 21.025,3.029 21.025,0.503 ; SB4.1 25.261,3.262 25.553,2.97 25.553,0.58 ; SB7.1 29.753,3.273 30.132,2.894 30.132,0.587 ; SB13.1@33.351,3.275 34.095,3.275 34.533,2.837 34.533,1.277 33.836,0.58 30.331,0.58 25.553,0.58
Red_LED_U5: R11.1 U1.18 | length 9.2
  Top Layer w0.25: v2(23.781,17.181) 23.781,15.872 23.809,15.844 U1.18@23.799,15.835 ; v2@28.928,13.682 R11.1@29.505,13.682
  Internal 1 w0.25: v2(23.781,17.181) 26.648,17.181 28.838,14.99 28.838,13.85 28.845,13.844 28.845,13.71 v2@28.838,13.704
  other v2: 28.883,13.664
RSTN: B2.2 B2.4 C2.2 CN1.12 R6.2 U1.14 U3.1 | length 38.4
  Top Layer w0.2: v2(23.219,13.165) 23.773,13.165 R6.2@23.783,13.175
  Top Layer w0.25: v2(8.283,27.421) 7.174,26.312 7.174,18.244 9.759,15.659 U1.14@13.559,15.659
  Top Layer w0.4: B2.4 13.597,14.236 C2.2 ; C2.2@13.597,14.265 U1.14@13.597,15.659 ; B2.2@13.612,12.399 v2(14.501,12.399)
  Internal 1 w0.4: v2(14.501,12.399) 22.519,12.399 v2@23.206,13.085
  Bottom Layer w0.4: CN1.12@6.003,27.443 6.025,27.421 v2(8.283,27.421)
SPI_CLK: CN2.11 U1.23 | length 10.3
  Top Layer w0.25: U1.23@31.539,23.426 31.579,23.467 v2(32.392,23.467)
  Bottom Layer w0.25: v2@32.386,23.436 32.386,23.475 32.28,23.581 32.241,23.581 31.27,24.551 31.27,26.794 31.915,27.438 CN2.11
SPI_CSn: CN2.21 U1.31 | length 27.3
  Top Layer w0.25: U1.31 33.431,43.679 35.627,41.483 35.627,21.841 v2(34.831,21.046)
  Bottom Layer w0.25: v2(34.831,21.046) 36.301,21.046 CN2.21@36.311,21.055
SPI_MISO: CN2.13 U1.24 | length 5.1
  Top Layer w0.25: U1.24@31.598,26.125 31.612,26.139 v2(32.395,26.139)
  Bottom Layer w0.25: v2(32.395,26.139) 36.69,26.139 CN2.13@36.724,26.106
SPI_MOSI: CN2.15 U1.22 | length 8.2
  Top Layer w0.25: U1.22 32.282,20.819 33.248,21.785 33.248,23.586 34.603,24.941 34.603,24.97 34.735,25.102 v2@34.764,25.102
  Bottom Layer w0.25: v2(34.703,25.124) 36.398,25.124 CN2.15
SWCLK: CN1.15 R4.2 U1.8 | length 40.7
  Top Layer w0.15: v2(4.159,24.934) 4.677,25.451 4.677,26.885 3.185,28.377 3.185,29.732 4.431,30.979 U1.8 ; R4.2@21.844,13.214 21.873,13.185 v2(22.439,13.185)
  Internal 1 w0.2: v2@9.949,30.973 12.52,30.973 19.996,23.497 19.996,15.628 v2(22.439,13.185)
  Bottom Layer w0.15: CN1.15@2.621,25.039 CN1.15@2.727,24.934
  Bottom Layer w0.2: CN1.15@2.727,24.934 v2(4.159,24.934)
  other v2: 9.98,30.992
SWDIO: CN1.13 R3.2 U1.7 | length 44.8
  Top Layer w0.2: v2(4.143,26.187) 4.095,26.235 3.86,26.235 1.705,28.39 1.705,30.093 5.132,33.519 U1.7 ; v2(18.125,13.18) 18.648,13.18 R3.2@18.672,13.204
  Internal 1 w0.2: v2(4.143,26.187) 4.143,26.805 5.34,28.001 12.69,28.001 18.135,22.557 v2@18.135,13.169
  Bottom Layer w0.2: CN1.13@2.56,26.163 2.58,26.183 4.163,26.183 4.159,26.187 v2(4.143,26.187)
UART_RX: CN2.43 U1.30 | length 41.7
  Top Layer w0.25: U1.30 v2@32.539,41.139
  Internal 1 w0.25: v2(32.593,41.141) 41.306,32.428 41.306,10.033 v2@38.403,7.129
  Bottom Layer w0.25: CN2.43 36.641,7.135 38.425,7.135 v2@38.434,7.143
  other v2: 38.394,7.152
UART_TX_HostWakeUp: CN2.45 U1.29 | length 40.9
  Top Layer w0.25: U1.29 32.555,38.599 v2@32.574,38.58
  Internal 1 w0.25: v2(32.632,38.58) 39.876,31.335 39.876,10.821 v2@34.836,5.78
  Bottom Layer w0.25: v2@34.8,5.809 36.585,5.809 CN2.45
  other v2: 34.824,5.801
UserBTN: C11.2 R1.1 U1.10 | length 19.2
  Top Layer w0.2: R1.1@8.924,11.065 R1.1@8.97,11.065 ; v2@8.97,11.761 R1.1@8.97,11.065 ; C11.2 10.093,11.065 R1.1@8.97,11.065 ; U1.10@11.187,25.968 11.197,25.958 v2(12.118,25.958)
  Internal 1 w0.2: v2(8.984,11.775) 13.07,15.861 13.07,25.085 12.166,25.989 v2@12.115,25.989
VCP1_RX: CN1.45 R7.1 TP1.1 U1.11 | length 64.4
  Top Layer w0.2: U1.11@11.09,23.323 U1.11@11.106,23.339 ; R7.1@26.888,5.051 26.906,5.068 v2(27.516,5.068)
  Top Layer w0.3: U1.11@11.106,23.339 v2(12.513,23.339)
  Internal 1 w0.2: TP1.1@2.457,1.234 3.449,2.225 3.449,6.246 ; v2(4.132,5.86) 4.11,5.883 3.812,5.883 3.449,6.246 ; v2(12.513,23.339) 12.511,23.342 6.627,23.342 3.449,20.164 3.449,6.246
  Bottom Layer w0.2: CN1.45@2.483,5.846 4.118,5.846 v2(4.132,5.86) ; v2(12.513,23.339) 12.516,23.342 21.177,23.342 28.227,16.292 28.227,5.779 v2(27.516,5.068)
VCP1_TX: CN1.47 R8.2 TP3.1 U1.12 | length 50.1
  Top Layer w0.15: R8.2 26.954,13.166 v2@27.556,13.166
  Top Layer w0.2: U1.12@10.981,20.843 U1.12@11.122,20.843 ; U1.12 U1.12@11.193,20.889
  Top Layer w0.3: U1.12@11.193,20.889 v2@12.458,20.889
  Internal 1 w0.2: v2(4.146,4.642) 4.589,4.642 ; 4.595,4.648 5.628,5.682 5.628,19.762 6.761,20.895 v2(12.531,20.895) ; 4.598,4.644 5.04,4.203 TP3.1@5.04,1.196
  Bottom Layer w0.2: CN1.47@2.91,4.639 4.143,4.639 v2(4.146,4.642) ; v2(12.531,20.895) 22.419,20.895 27.572,15.741 v2(27.572,13.187)
VDD_IO_1: SB9.2 SB10.2 SB11.2 U1.5 | length 42.7
  Top Layer w0.5: v2(9.999,38.606) 10.982,38.606 U1.5@11.006,38.63
  Internal 2 w0.5: v2(9.999,38.606) 9.252,37.859 9.252,15.648 v2(10.203,14.696) 10.133,14.626 10.133,10.722 v2(15.622,5.233)
  Bottom Layer w0.5: SB9.2 9.58,14.721 v2@10.199,14.721 ; v2(15.622,5.233) 16.693,4.161 SB10.2@19.868,4.161
VDD_IO_2: SB12.2 SB13.2 SB14.2 U1.33 | length 51.2
  Top Layer w0.5: U1.33@31.498,48.809 31.564,48.743 v2(32.492,48.743)
  Internal 2 w0.5: v2(32.492,48.743) 36.862,44.374 v2@36.862,38.508 ; v2(34.25,4.276) 34.264,4.276 36.858,6.871 v2(36.858,38.503)
  Bottom Layer w0.5: SB14.2 34.213,4.239 v2(34.25,4.276) ; SB12.2 36.848,38.477 v2@36.862,38.491
VDD_MCU: B1.1 B1.3 C10.2 CN3.3 R9.1 SB3.2 SB4.2 SB5.2 U1.16 | length 62.9
  Top Layer w0.5: v2@4.422,6.992 5.191,6.992 B1.3 5.26,12.168 B1.1@5.35,12.258 ; U1.16@18.68,15.648 18.657,15.671 18.657,16.25 18.803,16.396 v2(18.803,17.139) ; CN3.3@19.681,6.959 19.681,5.334 v2(19.704,5.311) 19.922,5.092 20.419,5.092 20.487,5.024 C10.2@20.487,4.937 ; v2(30.639,4.476) 30.646,4.469 31.54,4.469 R9.1@31.588,4.421
  Internal 2 w0.5: v2(4.401,6.957) 4.912,6.957 8.537,3.332 v2(10.383,3.332) 15.415,3.332 ; v2(18.803,17.139) 16.676,15.012 16.676,4.593 15.415,3.332 ; v2@19.699,5.276 19.699,4.417 18.613,3.332 ; v2(30.639,4.476) 29.496,3.332 18.613,3.332 ; 15.415,3.332 18.613,3.332
  Bottom Layer w0.5: SB3.2 10.325,3.317 v2@10.342,3.299 ; v2(19.704,5.311) 20.554,5.311 21.653,4.212 SB4.2@24.445,4.212
pads on no net: CART-1.1 CN1.2 CN1.3 CN1.4 CN1.5 CN1.8 CN1.10 CN1.11 CN1.16 CN1.18 CN1.19 CN1.20 CN1.21 CN1.23 CN1.24 CN1.27 CN1.29 CN1.30 CN1.33 CN1.35 CN1.36 CN1.38 CN1.39 CN1.41 CN1.42 CN1.43 CN1.44 CN1.48 CN2.3 CN2.4 CN2.5 CN2.6 CN2.7 CN2.9 CN2.10 CN2.12 CN2.16 CN2.18 CN2.19 CN2.22 CN2.24 CN2.28 CN2.30 CN2.31 CN2.33 CN2.34 CN2.36 CN2.40 CN2.41 CN2.42 CN2.46 CN2.47 CN2.48 CN2.49 CN3.2 CN3.8 CN3.9 CN3.10 CN3.NPTH1 CN3.NPTH2 U2.3 U2.5
copper on no net: | length 1348.4
  Top Layer w0.381: -0.847,93.55 9.565,93.55 33.18,93.55 55.019,93.55 71.524,93.55 85.999,93.55 ; -0.847,96.598 9.565,96.598 33.18,96.598 55.019,96.598 71.524,96.598 85.999,96.598 ; -0.847,99.646 9.565,99.646 33.18,99.646 55.019,99.646 71.524,99.646 85.999,99.646 ; -0.847,102.694 9.565,102.694 33.18,102.694 55.019,102.694 71.524,102.694 85.999,102.694 ; -0.847,105.742 9.565,105.742 33.18,105.742 55.019,105.742 71.524,105.742 85.999,105.742 ; -0.847,108.79 9.565,108.79 33.18,108.79 55.019,108.79 71.524,108.79 85.999,108.79 ; -0.847,111.838 9.565,111.838 33.18,111.838 55.019,111.838 71.524,111.838 85.999,111.838 ; -0.847,114.886 9.565,114.886 33.18,114.886 55.019,114.886 71.524,114.886 85.999,114.886 ; -0.847,117.934 9.565,117.934 33.18,117.934 55.019,117.934 71.524,117.934 85.999,117.934 ; -0.847,120.982 9.565,120.982 33.18,120.982 55.019,120.982 71.524,120.982 85.999,120.982 ; -0.847,124.03 85.999,124.03 ; 9.565,127.078 9.565,90.502 ; 33.18,127.078 33.18,90.502 ; 55.019,127.078 55.019,90.502 ; 71.524,127.078 71.524,90.502 ; 9.565,90.502 33.18,90.502 ; 9.565,90.502 -0.847,90.502 -0.847,127.078 85.999,127.078 85.999,90.502 71.524,90.502 ; 33.18,90.502 55.019,90.502 ; 55.019,90.502 71.524,90.502

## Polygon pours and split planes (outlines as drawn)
GND on Internal 2 "GND_L03_P011" (solid, pour order 11): 1.05,-0.3 0.05,0.7 0.05,49.765 42.925,49.765 42.925,0.873 41.761,-0.291 41.761,-0.296 41.756,-0.291 1.055,-0.291
GND on Internal 1 "GND_L02_P010" (solid, pour order 10): 1.05,-0.3 0.031,0.719 0.031,49.765 42.925,49.765 42.925,0.873 41.761,-0.291 41.761,-0.296 41.756,-0.291 1.055,-0.291
GND on Top Layer "GND_L01_P006" (solid, pour order 6): 1.05,-0.3 0.05,0.7 0.05,49.765 42.925,49.765 42.925,0.873 41.761,-0.291 41.761,-0.296 41.756,-0.291 1.055,-0.291
GND on Bottom Layer "GND_L04_P012" (solid, pour order 12): 1.05,-0.3 0.094,0.656 0.094,49.765 42.925,49.765 42.925,0.873 41.761,-0.291 41.761,-0.296 41.756,-0.291 1.055,-0.291

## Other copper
Top Layer:
  text "Layer" at 0.931,124.792 h1.52
  text "Name" at 11.343,124.792 h1.52
  text "Material" at 34.958,124.792 h1.52
  text "Thickness" at 56.797,124.792 h1.52
  text "Constant" at 73.302,124.792 h1.52
  text "Top Overlay" at 11.343,121.744 h1.52
  text "Top Solder" at 11.343,118.696 h1.52
  text "Solder Resist" at 34.958,118.696 h1.52
  text "0.70mil" at 56.797,118.696 h1.52
  text "3.2" at 73.302,118.696 h1.52
  text "1" at 0.931,115.648 h1.52
  text "Top Layer" at 11.343,115.648 h1.52
  text "1.60mil" at 56.797,115.648 h1.52
  text "Dielectric 1" at 11.343,112.6 h1.52
  text "FR-4" at 34.958,112.6 h1.52
  text "3.00mil" at 56.797,112.6 h1.52
  text "3.7" at 73.302,112.6 h1.52
  text "2" at 0.931,109.552 h1.52
  text "Internal 1" at 11.343,109.552 h1.52
  text "1.20mil" at 56.797,109.552 h1.52
  text "Dielectric 3" at 11.343,106.504 h1.52
  text "50.00mil" at 56.797,106.504 h1.52
  text "4.5" at 73.302,106.504 h1.52
  text "3" at 0.931,103.456 h1.52
  text "Internal 2" at 11.343,103.456 h1.52
  text "1.20mil" at 56.797,103.456 h1.52
  text "Dielectric 2" at 11.343,100.408 h1.52
  text "3.00mil" at 56.797,100.408 h1.52
  text "3.7" at 73.302,100.408 h1.52
  text "4" at 0.931,97.36 h1.52
  text "Bottom Layer" at 11.343,97.36 h1.52
  text "1.60mil" at 56.797,97.36 h1.52
  text "Bottom Solder" at 11.343,94.312 h1.52
  text "Solder Resist" at 34.958,94.312 h1.52
  text "0.70mil" at 56.797,94.312 h1.52
  text "4.2" at 73.302,94.312 h1.52
  text "Bottom Overlay" at 11.343,91.264 h1.52

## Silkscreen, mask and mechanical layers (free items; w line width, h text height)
Top Overlay:
  text "B2416" at 33.047,44.719 h2.5
  text "J" at 1.815,43.418 h10
  text "U5_rst" at 16.193,6.984 h0.8 r90
  text "E" at 36.754,6.925 h7
  text "U5_btn" at 3.275,6.565 h0.8 r90
  text "LED_U5" at 34.824,6.258 h0.8 r90
  text "STLinkV3" at 28.85,5.826 h0.8 r90
  text "UART_U5" at 1.193,4.244 h0.8
  text "V_IO1" at 17.416,3.184 h0.8
  text "AVDD" at 26.999,3.164 h0.8
  text "V_mcu" at 21.806,3.147 h0.8
  text "V_IO2" at 31.033,3.025 h0.8
  text "GND" at 37.64,3.039 h0.8
  text "RX" at 1.763,2.749 h0.8
  text "TX" at 4.356,2.739 h0.8
  text "GND" at 6.528,2.739 h0.8
  text "5V" at 9.532,2.689 h0.8
  text "-" at 25.878,0.113 h0.8 r90
  text "-" at 30.381,0.054 h0.8 r90
  text "-" at 34.918,0.054 h0.8 r90
  text "-" at 21.181,0.02 h0.8 r90
  text "+" at 26.315,-0.004 h0.8
  text "+" at 17.023,-0.096 h0.8
  text "+" at 30.666,-0.096 h0.8
  text "+" at 21.669,-0.13 h0.8
Bottom Overlay:
  text "J" at 41.745,43.642 h10
  text "C" at 7.93,43.241 h7.62
  text "H" at 7.328,39.751 h7.62
  text "I" at 40.707,38.667 h7.62
M1-Board Shape:
  lines w0.2: 42.995,0.868 42.986,0.86 41.86,-0.267 1.134,-0.267 1.126,-0.258 1.11,-0.258 0,0.852 0,49.689 0.044,49.733 42.994,49.733 43,49.728 43,0.868
M14-Top Assembly:
  lines w0.254: 18.244,49.318 ccw(c18.244,49.319) 18.244,49.319
Drill Drawing:
  circle w0.254: c1.794,69.35 r0.828
  lines w0.254: 0.966,72.25 2.623,72.25 2.623,73.907 0.966,73.907 0.966,72.25 ; 0.966,76.392 1.38,76.392 1.794,75.978 2.208,76.392 2.623,76.392 2.208,76.807 2.623,77.221 2.208,77.221 1.794,77.635 1.38,77.221 0.966,77.221 1.38,76.807 0.966,76.392 ; 0.966,79.706 1.794,80.121 2.623,79.706 2.208,80.535 2.623,81.363 1.794,80.949 0.966,81.363 1.38,80.535 0.966,79.706
  lines w0.381: -0.522,67.403 186.638,67.403 ; -0.522,82.316 186.638,82.316 ; 9.058,63.675 9.058,86.044 ; 17.857,63.675 17.857,86.044 ; 33.407,63.675 33.407,86.044 ; 40.835,63.675 40.835,86.044 ; 51.65,63.675 51.65,86.044 ; 72.149,63.675 72.149,86.044 ; 81.01,63.675 81.01,86.044 ; 92.586,63.675 92.586,86.044 ; 106.692,63.675 106.692,86.044 ; 118.318,63.675 118.318,86.044 ; 136.397,63.675 136.397,86.044 ; 153.99,63.675 153.99,86.044 ; 166.366,63.675 166.366,86.044 ; -0.522,63.675 186.638,63.675 186.638,86.044 -0.522,86.044 -0.522,63.675
  text "Symbol" at 1.715,83.434 h2.16
  text "Count" at 10.176,83.434 h2.16
  text "Hole Size" at 18.975,83.434 h2.16
  text "Plated" at 34.525,83.434 h2.16
  text "Hole Type" at 41.954,83.434 h2.16
  text "Drill Layer Pair" at 52.768,83.434 h2.16
  text "Via/Pad" at 73.267,83.434 h2.16
  text "Pad Shape" at 82.129,83.434 h2.16
  text "Template" at 93.705,83.434 h2.16
  text "Description" at 107.81,83.434 h2.16
  text "Hole Tolerance (+)" at 119.436,83.434 h2.16
  text "Hole Tolerance (-)" at 137.515,83.434 h2.16
  text "Hole Length" at 155.108,83.434 h2.16
  text "Routed Path Length" at 167.484,83.434 h2.16
  text "2" at 10.176,79.706 h1.8
  text "1.00mm (39.37mil)" at 18.975,79.706 h1.8
  text "NPTH" at 34.525,79.706 h1.8
  text "Round" at 41.954,79.706 h1.8
  text "Top Layer - Bottom Layer" at 52.768,79.706 h1.8
  text "Pad" at 73.267,79.706 h1.8
  text "Rounded" at 82.129,79.706 h1.8
  text "c0hn100m105p0" at 93.705,79.706 h1.8
  text "-" at 155.108,79.706 h1.8
  text "-" at 167.484,79.706 h1.8
  text "5" at 10.176,75.978 h1.8
  text "1.00mm (39.37mil)" at 18.975,75.978 h1.8
  text "PTH" at 34.525,75.978 h1.8
  text "Round" at 41.954,75.978 h1.8
  text "Top Layer - Bottom Layer" at 52.768,75.978 h1.8
  text "Pad" at 73.267,75.978 h1.8
  text "Rounded" at 82.129,75.978 h1.8
  text "c140h100m145" at 93.705,75.978 h1.8
  text "-" at 155.108,75.978 h1.8
  text "-" at 167.484,75.978 h1.8
  text "8" at 10.176,72.25 h1.8
  text "0.80mm (31.50mil)" at 18.975,72.25 h1.8
  text "PTH" at 34.525,72.25 h1.8
  text "Round" at 41.954,72.25 h1.8
  text "Top Layer - Bottom Layer" at 52.768,72.25 h1.8
  text "Pad" at 73.267,72.25 h1.8
  text "(Mixed)" at 82.129,72.25 h1.8
  text "(Mixed)" at 93.705,72.25 h1.8
  text "-" at 155.108,72.25 h1.8
  text "-" at 167.484,72.25 h1.8
  text "194" at 10.176,68.522 h1.8
  text "0.20mm (7.87mil)" at 18.975,68.522 h1.8
  text "PTH" at 34.525,68.522 h1.8
  text "Round" at 41.954,68.522 h1.8
  text "Top Layer - Bottom Layer" at 52.768,68.522 h1.8
  text "Via" at 73.267,68.522 h1.8
  text "Rounded" at 82.129,68.522 h1.8
  text "(Mixed)" at 93.705,68.522 h1.8
  text "-" at 155.108,68.522 h1.8
  text "-" at 167.484,68.522 h1.8
  text "209 Total" at 10.176,64.793 h1.8

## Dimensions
0.057,1.311 to 43.057,1.327 on M3-Top Dimensions
-0.061,49.733 to 1.133,-0.267 on M3-Top Dimensions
